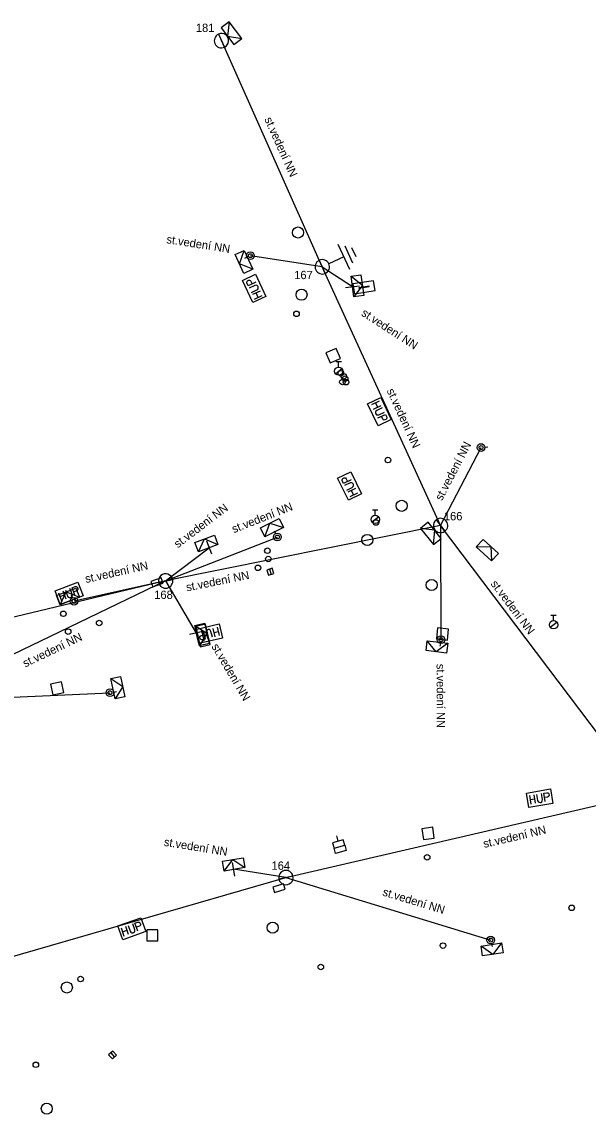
# Model space of a CAD drawing. Extents: x -584388 to -581645, y -1210859 to -1208922.
# Drawn here: x -583224.9 to -583173.8, y -1209575.4 to -1209476.8 of the extents above; entities that cross this region are included whole.
import ezdxf

# ---------------------------------------------------------------- set-up
doc = ezdxf.new("R2010")
doc.units = 0
for name, color, linetype in [('CIZÍ_NADZEM', 7, 'Continuous'), ('ELE_EON', 7, 'Continuous'), ('ELE_EON_POPIS', 7, 'Continuous')]:
    doc.layers.add(name, color=color, linetype=linetype)

msp = doc.modelspace()

# ---------------------------------------------------------------- linework, layer by layer
at = {"layer": 'CIZÍ_NADZEM'}
for p, q in [((-583196.568, -1209506.243), (-583197.487, -1209506.638)), ((-583196.173, -1209507.162), (-583196.568, -1209506.243)), ((-583197.487, -1209506.638), (-583197.092, -1209507.557)), ((-583197.092, -1209507.557), (-583196.173, -1209507.162)), ((-583196.58, -1209507.425), (-583196.08, -1209507.425)), ((-583196.33, -1209507.925), (-583196.33, -1209507.425)), ((-583196.624, -1209508.531), (-583196.034, -1209508.068)), ((-583193.28, -1209520.815), (-583192.78, -1209520.815)), ((-583193.03, -1209521.315), (-583193.03, -1209520.815)), ((-583193.324, -1209521.921), (-583192.734, -1209521.458)), ((-583202.566, -1209526.182), (-583202.414, -1209526.658)), ((-583177.224, -1209531.431), (-583176.634, -1209530.968)), ((-583177.18, -1209530.325), (-583176.68, -1209530.325)), ((-583176.93, -1209530.825), (-583176.93, -1209530.325)), ((-583187.392, -1209531.478), (-583187.502, -1209532.472)), ((-583186.398, -1209531.588), (-583187.392, -1209531.478)), ((-583186.508, -1209532.582), (-583186.398, -1209531.588)), ((-583187.502, -1209532.472), (-583186.508, -1209532.582)), ((-583221.356, -1209536.356), (-583222.334, -1209536.566)), ((-583222.334, -1209536.566), (-583222.124, -1209537.544)), ((-583221.146, -1209537.334), (-583221.356, -1209536.356)), ((-583222.124, -1209537.544), (-583221.146, -1209537.334)), ((-583187.839, -1209549.472), (-583188.828, -1209549.619)), ((-583188.828, -1209549.619), (-583188.681, -1209550.608)), ((-583187.692, -1209550.461), (-583187.839, -1209549.472)), ((-583196.537, -1209550.279), (-583196.398, -1209550.76)), ((-583188.681, -1209550.608), (-583187.692, -1209550.461)), ((-583212.66, -1209558.76), (-583213.66, -1209558.76)), ((-583213.66, -1209558.76), (-583213.66, -1209559.76)), ((-583212.66, -1209559.76), (-583212.66, -1209558.76)), ((-583213.66, -1209559.76), (-583212.66, -1209559.76)), ((-583216.906, -1209569.873), (-583216.574, -1209570.247))]:
    msp.add_line(p, q, dxfattribs=at)
for points in [[(-583204.086, -1209502.107), (-583205.023, -1209500.117), (-583203.828, -1209499.555), (-583202.892, -1209501.545), (-583204.086, -1209502.107)], [(-583204.493, -1209500.597), (-583204.615, -1209500.338), (-583204.62, -1209500.239), (-583204.602, -1209500.194), (-583204.55, -1209500.135), (-583204.45, -1209500.088), (-583204.371, -1209500.085), (-583204.325, -1209500.1), (-583204.253, -1209500.168), (-583204.131, -1209500.427)], [(-583203.796, -1209500.269), (-583204.493, -1209500.597)], [(-583204.212, -1209501.194), (-583203.712, -1209500.959), (-583203.628, -1209500.885), (-583203.591, -1209500.792), (-583203.597, -1209500.692), (-583203.624, -1209500.635), (-583203.697, -1209500.567), (-583203.79, -1209500.541), (-583203.901, -1209500.559), (-583204.4, -1209500.794)], [(-583203.422, -1209501.063), (-583204.119, -1209501.391)], [(-583203.931, -1209501.791), (-583203.234, -1209501.463)], [(-583203.602, -1209501.637), (-583203.791, -1209501.237)], [(-583192.519, -1209510.69), (-583191.576, -1209512.678), (-583192.769, -1209513.244), (-583193.711, -1209511.256), (-583192.519, -1209510.69)], [(-583192.673, -1209511.007), (-583193.369, -1209511.337)], [(-583193.179, -1209511.736), (-583192.484, -1209511.406)], [(-583193.001, -1209511.163), (-583192.812, -1209511.562)], [(-583192.39, -1209511.603), (-583192.889, -1209511.84), (-583192.973, -1209511.914), (-583193.01, -1209512.007), (-583193.004, -1209512.107), (-583192.977, -1209512.164), (-583192.903, -1209512.232), (-583192.81, -1209512.258), (-583192.699, -1209512.239), (-583192.201, -1209512.003)], [(-583192.803, -1209512.53), (-583192.107, -1209512.2)], [(-583192.107, -1209512.2), (-583191.985, -1209512.458), (-583191.979, -1209512.557), (-583191.997, -1209512.602), (-583192.049, -1209512.661), (-583192.148, -1209512.708), (-583192.227, -1209512.712), (-583192.273, -1209512.697), (-583192.346, -1209512.629), (-583192.469, -1209512.371)], [(-583195.454, -1209519.947), (-583196.419, -1209517.97), (-583195.232, -1209517.391), (-583194.268, -1209519.369), (-583195.454, -1209519.947)], [(-583195.882, -1209518.443), (-583196.008, -1209518.186), (-583196.015, -1209518.087), (-583195.997, -1209518.041), (-583195.946, -1209517.982), (-583195.847, -1209517.934), (-583195.768, -1209517.93), (-583195.722, -1209517.944), (-583195.648, -1209518.01), (-583195.523, -1209518.267)], [(-583195.19, -1209518.105), (-583195.882, -1209518.443)], [(-583195.593, -1209519.036), (-583195.097, -1209518.794), (-583195.013, -1209518.719), (-583194.977, -1209518.626), (-583194.985, -1209518.526), (-583195.012, -1209518.469), (-583195.087, -1209518.402), (-583195.18, -1209518.377), (-583195.29, -1209518.397), (-583195.787, -1209518.639)], [(-583194.805, -1209518.894), (-583195.497, -1209519.232)], [(-583195.303, -1209519.629), (-583194.611, -1209519.291)], [(-583194.977, -1209519.47), (-583195.171, -1209519.073)], [(-583221.925, -1209528.143), (-583219.867, -1209527.367), (-583219.401, -1209528.602), (-583221.459, -1209529.378), (-583221.925, -1209528.143)], [(-583220.937, -1209528.887), (-583221.209, -1209528.167)], [(-583221.005, -1209528.09), (-583220.81, -1209528.606), (-583220.743, -1209528.697), (-583220.653, -1209528.741), (-583220.553, -1209528.743), (-583220.494, -1209528.72), (-583220.42, -1209528.653), (-583220.387, -1209528.562), (-583220.396, -1209528.45), (-583220.591, -1209527.934)], [(-583220.387, -1209527.857), (-583220.12, -1209527.756), (-583220.021, -1209527.758), (-583219.977, -1209527.78), (-583219.923, -1209527.837), (-583219.884, -1209527.939), (-583219.887, -1209528.019), (-583219.905, -1209528.063), (-583219.978, -1209528.13), (-583220.246, -1209528.231)], [(-583220.115, -1209528.577), (-583220.387, -1209527.857)], [(-583221.622, -1209528.323), (-583221.35, -1209529.043)], [(-583221.494, -1209528.663), (-583221.081, -1209528.507)], [(-583206.814, -1209532.399), (-583208.954, -1209532.909), (-583209.26, -1209531.625), (-583207.12, -1209531.115), (-583206.814, -1209532.399)], [(-583208.375, -1209532.489), (-583208.654, -1209532.555), (-583208.752, -1209532.54), (-583208.792, -1209532.513), (-583208.839, -1209532.45), (-583208.865, -1209532.343), (-583208.851, -1209532.265), (-583208.827, -1209532.223), (-583208.746, -1209532.166), (-583208.468, -1209532.1)], [(-583208.554, -1209531.74), (-583208.375, -1209532.489)], [(-583207.733, -1209532.335), (-583207.862, -1209531.798), (-583207.917, -1209531.701), (-583208, -1209531.645), (-583208.099, -1209531.631), (-583208.16, -1209531.646), (-583208.242, -1209531.703), (-583208.286, -1209531.789), (-583208.292, -1209531.901), (-583208.163, -1209532.438)], [(-583207.7, -1209531.536), (-583207.521, -1209532.285)], [(-583207.176, -1209531.829), (-583207.606, -1209531.932)], [(-583207.091, -1209532.182), (-583207.27, -1209531.433)], [(-583179.374, -1209546.401), (-583177.205, -1209546.035), (-583176.985, -1209547.337), (-583179.155, -1209547.703), (-583179.374, -1209546.401)], [(-583179.111, -1209546.636), (-583178.983, -1209547.395)], [(-583179.051, -1209546.994), (-583178.615, -1209546.92)], [(-583178.548, -1209547.322), (-583178.676, -1209546.562)], [(-583178.461, -1209546.526), (-583178.369, -1209547.07), (-583178.32, -1209547.172), (-583178.241, -1209547.232), (-583178.143, -1209547.253), (-583178.081, -1209547.243), (-583177.996, -1209547.191), (-583177.946, -1209547.109), (-583177.933, -1209546.997), (-583178.025, -1209546.453)], [(-583177.81, -1209546.416), (-583177.528, -1209546.369), (-583177.431, -1209546.39), (-583177.392, -1209546.42), (-583177.35, -1209546.486), (-583177.332, -1209546.594), (-583177.35, -1209546.671), (-583177.377, -1209546.711), (-583177.461, -1209546.763), (-583177.743, -1209546.811)], [(-583177.682, -1209547.176), (-583177.81, -1209546.416)], [(-583195.78, -1209551.102), (-583195.641, -1209551.582), (-583196.602, -1209551.859), (-583196.74, -1209551.378)], [(-583216.265, -1209558.398), (-583214.188, -1209557.67), (-583213.752, -1209558.916), (-583215.828, -1209559.644), (-583216.265, -1209558.398)], [(-583215.966, -1209558.585), (-583215.711, -1209559.311)], [(-583215.846, -1209558.927), (-583215.429, -1209558.781)], [(-583215.294, -1209559.165), (-583215.549, -1209558.439)], [(-583215.343, -1209558.367), (-583215.161, -1209558.887), (-583215.096, -1209558.979), (-583215.007, -1209559.026), (-583214.907, -1209559.03), (-583214.848, -1209559.009), (-583214.772, -1209558.943), (-583214.737, -1209558.853), (-583214.744, -1209558.741), (-583214.926, -1209558.22)], [(-583214.72, -1209558.148), (-583214.45, -1209558.054), (-583214.351, -1209558.058), (-583214.308, -1209558.081), (-583214.255, -1209558.139), (-583214.219, -1209558.243), (-583214.224, -1209558.322), (-583214.244, -1209558.366), (-583214.318, -1209558.431), (-583214.588, -1209558.526)], [(-583214.466, -1209558.875), (-583214.72, -1209558.148)]]:
    msp.add_lwpolyline(points, dxfattribs=at)
for points in [[(-583202.805, -1209526.258), (-583202.653, -1209526.735), (-583202.175, -1209526.583), (-583202.327, -1209526.106)], [(-583213.12, -1209527.781), (-583212.176, -1209527.451), (-583212.34, -1209526.979), (-583213.284, -1209527.309)], [(-583195.918, -1209550.621), (-583196.879, -1209550.898), (-583196.74, -1209551.378), (-583195.78, -1209551.102)], [(-583202.113, -1209555.378), (-583201.158, -1209555.08), (-583201.307, -1209554.602), (-583202.262, -1209554.9)], [(-583217.094, -1209570.039), (-583216.762, -1209570.414), (-583216.386, -1209570.081), (-583216.718, -1209569.707)]]:
    msp.add_lwpolyline(points, close=True, dxfattribs=at)
for centre, radius in [((-583200, -1209495.78), 0.5), ((-583199.68, -1209501.4), 0.5), ((-583200.14, -1209503.12), 0.25), ((-583196.33, -1209508.3), 0.375), ((-583196.13, -1209508.49), 0.25), ((-583195.87, -1209508.76), 0.25), ((-583195.99, -1209509.28), 0.25), ((-583195.74, -1209508.98), 0.25), ((-583195.67, -1209509.29), 0.25), ((-583191.88, -1209516.33), 0.25), ((-583190.64, -1209520.46), 0.5), ((-583193.03, -1209521.69), 0.375), ((-583192.96, -1209521.97), 0.25), ((-583193.74, -1209523.54), 0.5), ((-583202.76, -1209524.52), 0.25), ((-583202.68, -1209525.26), 0.25), ((-583203.62, -1209526.06), 0.25), ((-583187.93, -1209527.61), 0.5), ((-583221.18, -1209530.21), 0.25), ((-583217.95, -1209531.04), 0.25), ((-583176.93, -1209531.2), 0.375), ((-583220.75, -1209531.82), 0.25), ((-583188.34, -1209552.21), 0.25), ((-583175.29, -1209556.77), 0.25), ((-583202.29, -1209558.56), 0.5), ((-583186.91, -1209560.18), 0.25), ((-583197.94, -1209562.11), 0.25), ((-583220.87, -1209563.96), 0.5), ((-583219.63, -1209563.2), 0.25), ((-583223.67, -1209570.94), 0.25), ((-583222.68, -1209574.9), 0.5)]:
    msp.add_circle(centre, radius, dxfattribs=at)
at = {"layer": 'ELE_EON'}
for p, q in [((-583207.174, -1209477.856), (-583206.646, -1209479.044)), ((-583195.335, -1209499.123), (-583196.374, -1209496.849)), ((-583195.047, -1209498.551), (-583195.753, -1209497.005)), ((-583194.758, -1209497.979), (-583195.132, -1209497.161)), ((-583204.616, -1209498.02), (-583204.842, -1209498.127)), ((-583198.08, -1209498.289), (-583197.54, -1209499.471)), ((-583195.855, -1209497.986), (-583197.219, -1209498.61)), ((-583195.701, -1209500.734), (-583194.459, -1209500.586)), ((-583183.122, -1209515.164), (-583182.873, -1209515.139)), ((-583187.522, -1209521.721), (-583186.738, -1209522.759)), ((-583202.014, -1209522.966), (-583202.124, -1209522.741)), ((-583207.794, -1209524.837), (-583208.226, -1209523.663)), ((-583212.587, -1209527.379), (-583211.313, -1209527.121)), ((-583220.348, -1209528.754), (-583220.44, -1209528.522)), ((-583208.581, -1209531.81), (-583209.799, -1209532.09)), ((-583187.148, -1209532.895), (-583187.189, -1209533.142)), ((-583216.635, -1209537.282), (-583216.388, -1209537.24)), ((-583205.702, -1209553.896), (-583205.918, -1209552.664)), ((-583200.457, -1209553.893), (-583201.723, -1209554.187)), ((-583182.532, -1209560.023), (-583182.484, -1209560.269))]:
    msp.add_line(p, q, dxfattribs=at)
for points in [[(-583206.922, -1209477.29), (-583205.803, -1209478.795), (-583205.081, -1209478.258), (-583206.2, -1209476.753)], [(-583204.888, -1209499.471), (-583205.683, -1209497.772), (-583204.867, -1209497.391), (-583204.073, -1209499.089)], [(-583194.315, -1209499.609), (-583194.062, -1209501.467), (-583194.953, -1209501.589), (-583195.207, -1209499.731)], [(-583193.184, -1209500.132), (-583195.036, -1209500.428), (-583194.894, -1209501.316), (-583193.043, -1209501.021)], [(-583193.579, -1209500.632), (-583194.505, -1209500.78), (-583194.499, -1209500.817), (-583193.573, -1209500.669)], [(-583203.391, -1209522.454), (-583201.714, -1209521.616), (-583201.311, -1209522.421), (-583202.989, -1209523.259)], [(-583187.066, -1209523.398), (-583188.252, -1209521.945), (-583188.949, -1209522.514), (-583187.763, -1209523.967)], [(-583209.305, -1209523.779), (-583207.55, -1209523.117), (-583207.233, -1209523.959), (-583208.987, -1209524.621)], [(-583183.297, -1209523.493), (-583181.911, -1209524.756), (-583182.517, -1209525.422), (-583183.903, -1209524.158)], [(-583221.799, -1209528.558), (-583220.05, -1209527.883), (-583219.725, -1209528.722), (-583221.475, -1209529.398)], [(-583208.446, -1209531.063), (-583208.021, -1209532.889), (-583208.898, -1209533.093), (-583209.322, -1209531.267)], [(-583209.218, -1209531.354), (-583208.822, -1209533.186), (-583207.942, -1209532.996), (-583208.338, -1209531.163)], [(-583208.698, -1209531.721), (-583208.499, -1209532.637), (-583208.463, -1209532.629), (-583208.661, -1209531.713)], [(-583186.582, -1209533.77), (-583188.443, -1209533.536), (-583188.33, -1209532.643), (-583186.47, -1209532.877)], [(-583216.016, -1209535.865), (-583215.624, -1209537.699), (-583216.504, -1209537.887), (-583216.896, -1209536.053)], [(-583206.803, -1209552.556), (-583204.953, -1209552.248), (-583204.805, -1209553.136), (-583206.655, -1209553.444)], [(-583181.481, -1209560.833), (-583183.335, -1209561.108), (-583183.467, -1209560.218), (-583181.613, -1209559.942)]]:
    msp.add_lwpolyline(points, close=True, dxfattribs=at)
for points in [[(-583206.2, -1209476.753), (-583206.362, -1209478.043), (-583205.081, -1209478.258)], [(-583197.81, -1209498.88), (-583206.91, -1209478.45)], [(-583204.073, -1209499.089), (-583205.285, -1209498.621), (-583204.867, -1209497.391)], [(-583197.81, -1209498.88), (-583204.3, -1209497.87)], [(-583187.13, -1209522.24), (-583197.81, -1209498.88)], [(-583197.81, -1209498.88), (-583195.08, -1209500.66)], [(-583195.207, -1209499.731), (-583194.188, -1209500.538), (-583194.953, -1209501.589)], [(-583187.13, -1209522.24), (-583183.47, -1209515.2)], [(-583187.13, -1209522.24), (-583211.95, -1209527.25)], [(-583202.989, -1209523.259), (-583202.552, -1209522.035), (-583201.311, -1209522.421)], [(-583187.13, -1209522.24), (-583187.09, -1209532.55)], [(-583168.79, -1209546.54), (-583187.13, -1209522.24)], [(-583211.95, -1209527.25), (-583201.86, -1209523.28)], [(-583187.763, -1209523.967), (-583187.659, -1209522.672), (-583188.949, -1209522.514)], [(-583211.95, -1209527.25), (-583208.01, -1209524.25)], [(-583208.987, -1209524.621), (-583208.428, -1209523.448), (-583207.233, -1209523.959)], [(-583183.903, -1209524.158), (-583182.604, -1209524.125), (-583182.517, -1209525.422)], [(-583211.95, -1209527.25), (-583234.57, -1209538.13)], [(-583211.95, -1209527.25), (-583228.98, -1209531.29)], [(-583211.95, -1209527.25), (-583220.22, -1209529.08)], [(-583211.95, -1209527.25), (-583209.19, -1209531.95)], [(-583221.475, -1209529.398), (-583220.924, -1209528.22), (-583219.725, -1209528.722)], [(-583209.322, -1209531.267), (-583208.233, -1209531.976), (-583208.898, -1209533.093)], [(-583186.47, -1209532.877), (-583187.513, -1209533.653), (-583188.33, -1209532.643)], [(-583216.896, -1209536.053), (-583215.82, -1209536.782), (-583216.504, -1209537.887)], [(-583234.57, -1209538.13), (-583216.98, -1209537.34)], [(-583201.09, -1209554.04), (-583168.79, -1209546.54)], [(-583206.655, -1209553.444), (-583205.878, -1209552.402), (-583204.805, -1209553.136)], [(-583201.09, -1209554.04), (-583205.81, -1209553.28)], [(-583260.82, -1209570.08), (-583227.8, -1209561.74), (-583201.09, -1209554.04)], [(-583201.09, -1209554.04), (-583182.6, -1209559.68)], [(-583181.613, -1209559.942), (-583182.408, -1209560.97), (-583183.467, -1209560.218)]]:
    msp.add_lwpolyline(points, dxfattribs=at)
for centre, radius in [((-583204.3, -1209497.87), 0.35), ((-583204.3, -1209497.87), 0.175), ((-583183.47, -1209515.2), 0.35), ((-583183.47, -1209515.2), 0.175), ((-583201.86, -1209523.28), 0.35), ((-583201.86, -1209523.28), 0.175), ((-583220.22, -1209529.08), 0.35), ((-583220.22, -1209529.08), 0.175), ((-583187.09, -1209532.55), 0.35), ((-583187.09, -1209532.55), 0.175), ((-583216.98, -1209537.34), 0.35), ((-583216.98, -1209537.34), 0.175), ((-583182.6, -1209559.68), 0.35), ((-583182.6, -1209559.68), 0.175)]:
    msp.add_circle(centre, radius, dxfattribs=at)
for centre, start, end in [((-583206.91, -1209478.45), 114.00932, 294.00932), ((-583206.91, -1209478.45), 294.00932, 114.00932), ((-583197.81, -1209498.88), 114.5695, 294.5695), ((-583197.81, -1209498.88), 294.5695, 114.5695), ((-583187.13, -1209522.24), 127.04302, 307.04302), ((-583187.13, -1209522.24), 307.04302, 127.04302), ((-583211.95, -1209527.25), 11.41202, 191.41202), ((-583211.95, -1209527.25), 191.41202, 11.41202), ((-583201.09, -1209554.04), 13.07232, 193.07232), ((-583201.09, -1209554.04), 193.07232, 13.07232)]:
    msp.add_arc(centre, 0.65, start, end, dxfattribs=at)

# ---------------------------------------------------------------- texts
at = {"layer": 'ELE_EON_POPIS'}
for s, p in [('181', (-583209.22, -1209477.67)), ('167', (-583200.34, -1209499.99)), ('166', (-583186.83, -1209521.77)), ('168', (-583212.98, -1209528.87)), ('164', (-583202.39, -1209553.33))]:
    msp.add_text(s, height=0.75, dxfattribs=at).set_placement(p)
for rotation, p in [(294.00928, (-583203.05, -1209485.55)), (351.15437, (-583211.92, -1209496.74)), (326.89505, (-583194.35, -1209503.22)), (294.56946, (-583192.01, -1209510.06)), (62.53067, (-583187.01, -1209520.06)), (37.28643, (-583210.85, -1209524.31)), (21.47761, (-583205.8, -1209522.94)), (12.47747, (-583219.14, -1209527.44)), (11.412, (-583210.03, -1209528.2)), (307.04304, (-583182.65, -1209527.52)), (25.68713, (-583224.63, -1209535.07)), (300.42291, (-583207.84, -1209533.16)), (270.22231, (-583187.49, -1209534.73)), (13.07232, (-583183.19, -1209551.36)), (350.85294, (-583212.15, -1209551.16)), (343.03671, (-583192.42, -1209555.64))]:
    msp.add_text('st.vedení NN', height=0.75, rotation=rotation, dxfattribs=at).set_placement(p)

doc.saveas('drawing.dxf')
